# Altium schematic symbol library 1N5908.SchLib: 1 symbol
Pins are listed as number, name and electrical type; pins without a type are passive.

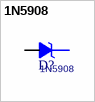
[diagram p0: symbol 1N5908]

## 1N5908
designator D?
footprint ST_DO201
pins: 1 K, 2 A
